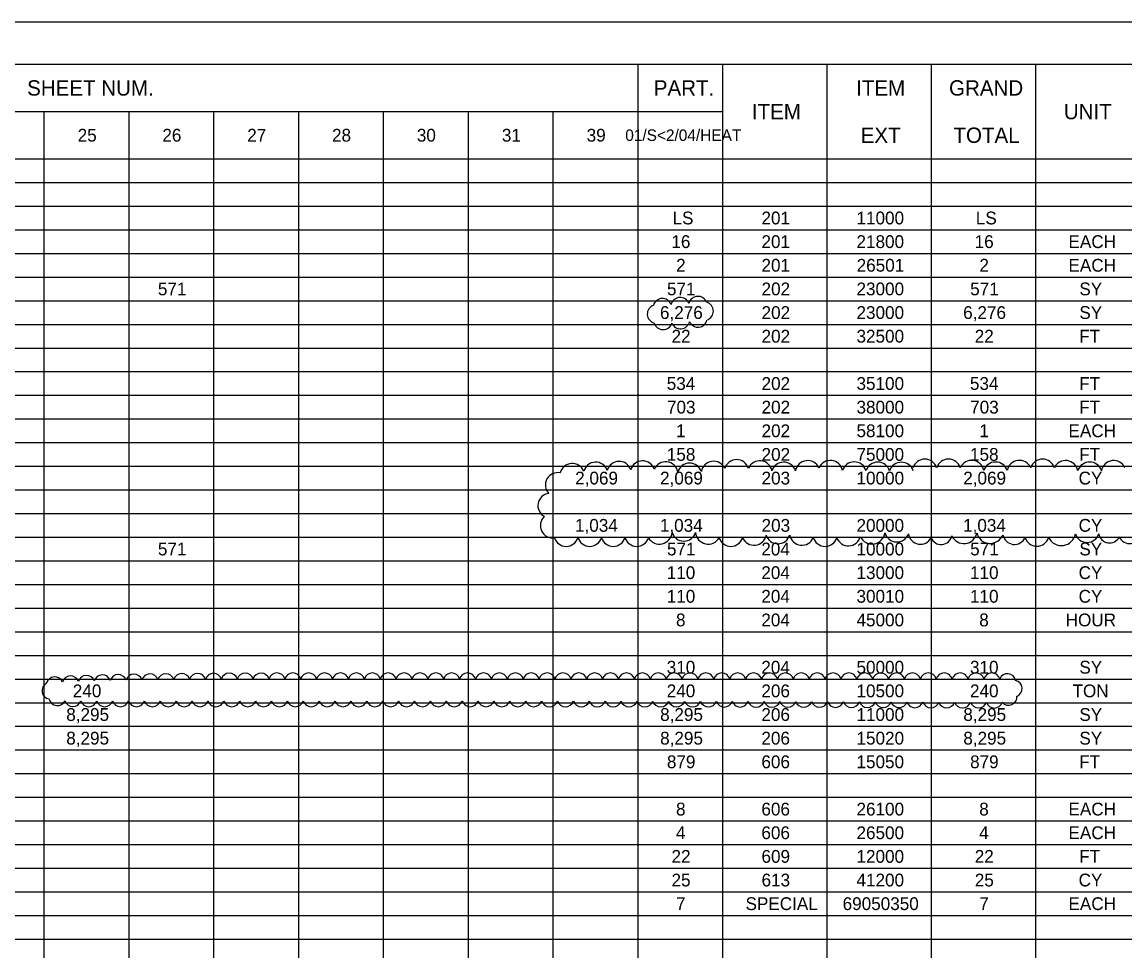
# Model space of a CAD drawing. Extents: x 0 to 36.7, y 0 to 22.
# Drawn here: x 7.27 to 20.33, y 11 to 22 of the extents above; entities that cross this region are included whole.
import ezdxf

# ---------------------------------------------------------------- set-up
doc = ezdxf.new("R2010")
doc.units = 0
for name, color, linetype in [('Default', 7, 'Continuous'), ('SC_Scratch2', 7, 'Continuous'), ('SH_Border', 7, 'Continuous'), ('SH_Cut_Line', 7, 'Continuous')]:
    doc.layers.add(name, color=color, linetype=linetype)

msp = doc.modelspace()

# ---------------------------------------------------------------- linework, layer by layer
at = {"layer": 'Default'}
for p, q in [((1.5, 21.5), (32, 21.5)), ((14.56, 21.5), (14.56, 0.5)), ((15.564, 21.5), (15.564, 0.5)), ((16.799, 21.5), (16.799, 0.5)), ((18.035, 21.5), (18.035, 0.5)), ((19.27, 21.5), (19.27, 0.5)), ((1.5, 20.94), (15.564, 20.94)), ((7.528, 20.94), (7.528, 0.5)), ((8.532, 20.94), (8.532, 0.5)), ((9.537, 20.94), (9.537, 0.5)), ((10.541, 20.94), (10.541, 0.5)), ((11.546, 20.94), (11.546, 0.5)), ((12.55, 20.94), (12.55, 0.5)), ((13.555, 20.94), (13.555, 0.5)), ((1.5, 20.38), (32, 20.38)), ((1.5, 20.1), (32, 20.1)), ((1.5, 19.82), (32, 19.82)), ((1.5, 19.54), (32, 19.54)), ((1.5, 19.26), (32, 19.26)), ((1.5, 18.98), (32, 18.98)), ((1.5, 18.7), (32, 18.7)), ((1.5, 18.42), (32, 18.42)), ((1.5, 18.14), (32, 18.14)), ((1.5, 17.86), (32, 17.86)), ((1.5, 17.58), (32, 17.58)), ((1.5, 17.3), (32, 17.3)), ((1.5, 17.02), (32, 17.02)), ((1.5, 16.74), (32, 16.74)), ((1.5, 16.46), (32, 16.46)), ((1.5, 16.18), (32, 16.18)), ((1.5, 15.9), (32, 15.9)), ((1.5, 15.62), (32, 15.62)), ((1.5, 15.34), (32, 15.34)), ((1.5, 15.06), (32, 15.06)), ((1.5, 14.78), (32, 14.78)), ((1.5, 14.5), (32, 14.5)), ((1.5, 14.22), (32, 14.22)), ((1.5, 13.94), (32, 13.94)), ((1.5, 13.66), (32, 13.66)), ((1.5, 13.38), (32, 13.38)), ((1.5, 13.1), (32, 13.1)), ((1.5, 12.82), (32, 12.82)), ((1.5, 12.54), (32, 12.54)), ((1.5, 12.26), (32, 12.26)), ((1.5, 11.98), (32, 11.98)), ((1.5, 11.7), (32, 11.7)), ((1.5, 11.42), (32, 11.42)), ((1.5, 11.14), (32, 11.14))]:
    msp.add_line(p, q, dxfattribs=at)
at = {"layer": 'SC_Scratch2'}
for centre, radius, start, end in [((14.851, 18.617), 0.11, 20.4379, 165.4379), ((15.061, 18.629), 0.11, 20.96, 165.96), ((15.272, 18.642), 0.11, 21.0791, 166.0791), ((15.344, 18.576), 0.11, 288.5716, 73.5716), ((14.782, 18.542), 0.11, 110.3076, 255.3076), ((14.859, 18.468), 0.11, 197.4518, 342.4518), ((15.065, 18.476), 0.11, 202.0873, 347.0873), ((15.273, 18.494), 0.108, 202.9538, 347.9538), ((13.783, 16.627), 0.146, 21.4169, 166.4169), ((14.06, 16.642), 0.146, 19.6954, 164.6954), ((14.338, 16.651), 0.146, 19.0371, 164.0371), ((14.616, 16.658), 0.146, 18.6594, 163.6594), ((14.889, 16.645), 0.147, 11.1599, 156.1599), ((15.173, 16.631), 0.146, 18.2211, 163.2211), ((15.457, 16.652), 0.147, 25.3014, 170.3014), ((15.73, 16.672), 0.146, 17.9636, 162.9636), ((16.004, 16.657), 0.147, 10.8854, 155.8854), ((16.287, 16.642), 0.146, 17.7891, 162.7891), ((16.571, 16.66), 0.147, 24.6956, 169.6956), ((16.839, 16.661), 0.147, 10.707, 155.707), ((17.123, 16.645), 0.146, 17.6083, 162.6083), ((17.401, 16.643), 0.146, 16.7917, 161.7917), ((17.68, 16.642), 0.146, 17.5196, 162.5196), ((17.959, 16.679), 0.146, 17.5, 162.5), ((18.238, 16.679), 0.146, 17.5, 162.5), ((18.511, 16.662), 0.147, 10.3144, 155.3144), ((18.795, 16.644), 0.146, 17.5, 162.5), ((19.079, 16.662), 0.147, 24.6856, 169.6856), ((19.352, 16.679), 0.146, 17.5, 162.5), ((19.625, 16.661), 0.147, 10.1962, 155.1962), ((19.91, 16.644), 0.146, 17.5, 162.5), ((20.194, 16.661), 0.147, 24.8038, 169.8038), ((13.611, 16.518), 0.146, 78.2198, 223.2198), ((13.522, 16.273), 0.146, 96.8264, 241.8264), ((13.552, 16.037), 0.146, 132.7451, 277.7451), ((14.816, 15.968), 0.15, 210.0865, 355.0865), ((15.105, 15.999), 0.146, 197.5, 342.5), ((15.393, 15.968), 0.15, 184.9135, 329.9135), ((17.333, 15.974), 0.155, 206.5092, 351.5092), ((17.627, 15.989), 0.146, 195.0241, 340.0241), ((17.905, 15.958), 0.142, 187.6612, 332.6612), ((18.421, 15.979), 0.155, 204.1248, 349.1248), ((18.731, 15.988), 0.162, 193.3553, 338.3553), ((19.576, 15.968), 0.168, 205.2375, 350.2375), ((19.88, 15.984), 0.146, 197.9428, 342.9428), ((20.146, 15.96), 0.128, 188.3479, 333.3479), ((20.383, 15.959), 0.135, 204.6591, 349.6591), ((13.711, 15.937), 0.146, 197.5, 342.5), ((13.99, 15.937), 0.146, 197.5, 342.5), ((14.269, 15.937), 0.146, 197.5, 342.5), ((14.547, 15.937), 0.146, 197.5, 342.5), ((15.662, 15.937), 0.146, 197.5, 342.5), ((15.936, 15.952), 0.147, 203.9369, 348.9369), ((16.219, 15.968), 0.146, 197.5, 342.5), ((16.503, 15.952), 0.147, 191.0631, 336.0631), ((16.777, 15.937), 0.146, 197.5, 342.5), ((17.053, 15.943), 0.146, 199.9759, 344.9759), ((18.151, 15.944), 0.131, 202.8141, 347.8141), ((19.019, 15.953), 0.139, 190.3783, 335.3783), ((19.284, 15.939), 0.146, 197.7653, 342.7653), ((7.656, 14.147), 0.0986, 21.8783, 166.8783), ((7.843, 14.158), 0.0986, 20.1463, 165.1463), ((8.031, 14.165), 0.0986, 19.4158, 164.4158), ((8.219, 14.171), 0.0986, 18.9841, 163.9841), ((8.407, 14.175), 0.0986, 18.6903, 163.6903), ((8.595, 14.179), 0.0986, 18.4736, 163.4736), ((8.783, 14.182), 0.0986, 18.3053, 163.3053), ((8.971, 14.184), 0.0986, 18.1697, 163.1697), ((9.159, 14.186), 0.0986, 18.0573, 163.0573), ((9.347, 14.188), 0.0986, 17.9622, 162.9622), ((9.535, 14.189), 0.0986, 17.8805, 162.8805), ((9.723, 14.191), 0.0986, 17.8091, 162.8091), ((9.911, 14.191), 0.0986, 17.7462, 162.7462), ((10.099, 14.192), 0.0986, 17.6901, 162.6901), ((10.287, 14.193), 0.0986, 17.6398, 162.6398), ((10.475, 14.193), 0.0986, 17.5942, 162.5942), ((10.663, 14.193), 0.0986, 17.5527, 162.5527), ((10.851, 14.193), 0.0986, 17.5149, 162.5149), ((11.039, 14.193), 0.0986, 17.5, 162.5), ((11.227, 14.193), 0.0986, 17.5, 162.5), ((11.416, 14.193), 0.0986, 17.5, 162.5), ((11.604, 14.193), 0.0986, 17.5, 162.5), ((11.792, 14.193), 0.0986, 17.5, 162.5), ((11.98, 14.193), 0.0986, 17.5, 162.5), ((12.168, 14.193), 0.0986, 17.5, 162.5), ((12.356, 14.193), 0.0986, 17.5, 162.5), ((12.544, 14.193), 0.0986, 17.5, 162.5), ((12.732, 14.193), 0.0986, 17.5, 162.5), ((12.92, 14.193), 0.0986, 17.5, 162.5), ((13.109, 14.193), 0.0986, 17.5, 162.5), ((13.297, 14.193), 0.0986, 17.5, 162.5), ((13.485, 14.193), 0.0986, 17.5, 162.5), ((13.673, 14.193), 0.0986, 17.5, 162.5), ((13.861, 14.193), 0.0986, 17.5, 162.5), ((14.049, 14.193), 0.0986, 17.5, 162.5), ((14.237, 14.193), 0.0986, 17.5, 162.5), ((14.425, 14.193), 0.0986, 17.5, 162.5), ((14.613, 14.193), 0.0986, 17.5, 162.5), ((14.802, 14.193), 0.0986, 17.5, 162.5), ((14.99, 14.193), 0.0986, 17.5, 162.5), ((15.178, 14.193), 0.0986, 17.5, 162.5), ((15.366, 14.193), 0.0986, 17.5, 162.5), ((15.554, 14.193), 0.0986, 17.5, 162.5), ((15.742, 14.193), 0.0986, 17.5, 162.5), ((15.93, 14.193), 0.0986, 17.5, 162.5), ((16.118, 14.193), 0.0986, 17.5, 162.5), ((16.306, 14.193), 0.0986, 17.5, 162.5), ((16.495, 14.193), 0.0986, 17.5, 162.5), ((16.683, 14.193), 0.0986, 17.5, 162.5), ((16.871, 14.193), 0.0986, 17.5, 162.5), ((17.059, 14.193), 0.0986, 17.5, 162.5), ((17.247, 14.193), 0.0986, 17.5, 162.5), ((17.435, 14.193), 0.0986, 17.5, 162.5), ((17.623, 14.193), 0.0986, 17.5, 162.5), ((17.811, 14.193), 0.0986, 17.5, 162.5), ((17.999, 14.193), 0.0986, 17.5, 162.5), ((18.188, 14.193), 0.0986, 17.5, 162.5), ((18.376, 14.193), 0.0986, 17.5, 162.5), ((18.564, 14.193), 0.0986, 17.5, 162.5), ((18.752, 14.193), 0.0986, 17.5, 162.5), ((18.936, 14.184), 0.0986, 11.6249, 156.6249), ((7.604, 14.081), 0.0985, 116.5401, 261.5401), ((19.012, 14.108), 0.0986, 292.4476, 77.4476), ((7.687, 14.003), 0.0986, 191.4507, 336.4507), ((18.951, 14.008), 0.0986, 219.9453, 4.9453), ((7.871, 13.992), 0.0986, 196.8954, 341.8954), ((8.059, 13.991), 0.0986, 197.5, 342.5), ((8.247, 13.991), 0.0986, 197.5, 342.5), ((8.435, 13.991), 0.0986, 197.5, 342.5), ((8.623, 13.991), 0.0986, 197.5, 342.5), ((8.812, 13.991), 0.0986, 197.5, 342.5), ((9, 13.991), 0.0986, 197.5, 342.5), ((9.188, 13.991), 0.0986, 197.5, 342.5), ((9.376, 13.991), 0.0986, 197.5, 342.5), ((9.564, 13.991), 0.0986, 197.5, 342.5), ((9.752, 13.991), 0.0986, 197.5, 342.5), ((9.94, 13.991), 0.0986, 197.5, 342.5), ((10.128, 13.991), 0.0986, 197.5, 342.5), ((10.316, 13.991), 0.0986, 197.5, 342.5), ((10.505, 13.991), 0.0986, 197.5, 342.5), ((10.693, 13.991), 0.0986, 197.5, 342.5), ((10.881, 13.991), 0.0986, 197.5, 342.5), ((11.069, 13.991), 0.0986, 197.5, 342.5), ((11.257, 13.991), 0.0986, 197.5, 342.5), ((11.445, 13.991), 0.0986, 197.5, 342.5), ((11.633, 13.991), 0.0986, 197.4999, 342.4999), ((11.821, 13.991), 0.0986, 197.4971, 342.4971), ((12.009, 13.991), 0.0986, 197.493, 342.493), ((12.198, 13.991), 0.0986, 197.4887, 342.4887), ((12.386, 13.991), 0.0986, 197.4843, 342.4843), ((12.574, 13.991), 0.0986, 197.4797, 342.4797), ((12.762, 13.991), 0.0986, 197.4749, 342.4749), ((12.95, 13.991), 0.0986, 197.4698, 342.4698), ((13.138, 13.991), 0.0986, 197.4646, 342.4646), ((13.326, 13.991), 0.0986, 197.4591, 342.4591), ((13.514, 13.99), 0.0986, 197.4534, 342.4534), ((13.702, 13.99), 0.0986, 197.4474, 342.4474), ((13.891, 13.99), 0.0986, 197.4411, 342.4411), ((14.079, 13.99), 0.0986, 197.4345, 342.4345), ((14.267, 13.99), 0.0986, 197.4276, 342.4276), ((14.455, 13.989), 0.0986, 197.4202, 342.4202), ((14.643, 13.989), 0.0986, 197.4125, 342.4125), ((14.831, 13.989), 0.0986, 197.4042, 342.4042), ((15.019, 13.989), 0.0986, 197.3955, 342.3955), ((15.207, 13.988), 0.0986, 197.3862, 342.3862), ((15.395, 13.988), 0.0986, 197.3763, 342.3763), ((15.584, 13.987), 0.0986, 197.3657, 342.3657), ((15.772, 13.987), 0.0986, 197.3544, 342.3544), ((15.96, 13.986), 0.0986, 197.3421, 342.3421), ((16.148, 13.986), 0.0986, 197.3289, 342.3289), ((16.336, 13.985), 0.0986, 197.3145, 342.3145), ((16.524, 13.985), 0.0986, 197.2987, 342.2987), ((16.712, 13.984), 0.0986, 197.2815, 342.2815), ((16.9, 13.983), 0.0986, 197.2625, 342.2625), ((17.088, 13.982), 0.0986, 197.2432, 342.2432), ((17.277, 13.982), 0.0986, 197.2392, 342.2392), ((17.465, 13.981), 0.0986, 197.2392, 342.2392), ((17.653, 13.98), 0.0986, 197.2392, 342.2392), ((17.841, 13.979), 0.0986, 197.2392, 342.2392), ((18.029, 13.978), 0.0986, 197.2392, 342.2392), ((18.217, 13.977), 0.0986, 197.2392, 342.2392), ((18.405, 13.976), 0.0986, 197.2392, 342.2392), ((18.593, 13.976), 0.0986, 197.2392, 342.2392), ((18.781, 13.975), 0.0986, 197.2392, 342.2392)]:
    msp.add_arc(centre, radius, start, end, dxfattribs=at)
at = {"layer": 'SH_Border'}
msp.add_lwpolyline([(1.5, 21.5), (33.5, 21.5), (33.5, 0.5), (1.5, 0.5)], close=True, dxfattribs=at)
at = {"layer": 'SH_Cut_Line'}
msp.add_lwpolyline([(0, 0), (34, 0), (34, 22), (0, 22)], close=True, dxfattribs=at)

# ---------------------------------------------------------------- texts
at = {"layer": 'Default'}
for s, height, p in [('SHEET NUM.', 0.1818, (7.329, 21.129)), ('PART.', 0.1818, (14.749, 21.129)), ('ITEM', 0.1818, (17.145, 21.129)), ('GRAND', 0.1818, (18.245, 21.129)), ('ITEM', 0.1818, (15.91, 20.849)), ('UNIT', 0.1818, (19.604, 20.849)), ('25', 0.1515, (7.927, 20.584)), ('26', 0.1515, (8.93, 20.584)), ('27', 0.1515, (9.935, 20.584)), ('28', 0.1515, (10.939, 20.584)), ('30', 0.1515, (11.943, 20.584)), ('31', 0.1515, (12.95, 20.584)), ('39', 0.1515, (13.954, 20.584)), ('01/S<2/04/HEAT', 0.13638, (14.411, 20.592)), ('EXT', 0.1818, (17.199, 20.569)), ('TOTAL', 0.1818, (18.297, 20.569)), ('LS', 0.1515, (14.971, 19.604)), ('201', 0.1515, (16.024, 19.604)), ('11000', 0.1515, (17.149, 19.604)), ('LS', 0.1515, (18.562, 19.604)), ('16', 0.1515, (14.957, 19.324)), ('201', 0.1515, (16.024, 19.324)), ('21800', 0.1515, (17.149, 19.324)), ('16', 0.1515, (18.548, 19.324)), ('EACH', 0.1515, (19.659, 19.324)), ('2', 0.152, (15.013, 19.044)), ('201', 0.1515, (16.024, 19.044)), ('26501', 0.1515, (17.151, 19.044)), ('2', 0.152, (18.604, 19.044)), ('EACH', 0.1515, (19.659, 19.044)), ('571', 0.1515, (8.877, 18.764)), ('571', 0.1515, (14.905, 18.764)), ('202', 0.1515, (16.025, 18.764)), ('23000', 0.1515, (17.149, 18.764)), ('571', 0.1515, (18.495, 18.764)), ('SY', 0.1515, (19.788, 18.764)), ('6,276', 0.1515, (14.822, 18.484)), ('202', 0.1515, (16.025, 18.484)), ('23000', 0.1515, (17.149, 18.484)), ('6,276', 0.1515, (18.412, 18.484)), ('SY', 0.1515, (19.788, 18.484)), ('22', 0.1515, (14.959, 18.204)), ('202', 0.1515, (16.025, 18.204)), ('32500', 0.1515, (17.149, 18.204)), ('22', 0.1515, (18.549, 18.204)), ('FT', 0.1515, (19.786, 18.204)), ('534', 0.1515, (14.902, 17.644)), ('202', 0.1515, (16.025, 17.644)), ('35100', 0.1515, (17.149, 17.644)), ('534', 0.1515, (18.492, 17.644)), ('FT', 0.1515, (19.786, 17.644)), ('703', 0.1515, (14.905, 17.364)), ('202', 0.1515, (16.025, 17.364)), ('38000', 0.1515, (17.149, 17.364)), ('703', 0.1515, (18.495, 17.364)), ('FT', 0.1515, (19.786, 17.364)), ('202', 0.1515, (16.025, 17.084)), ('58100', 0.1515, (17.149, 17.084)), ('EACH', 0.1515, (19.659, 17.084)), ('1', 0.152, (15.013, 17.084)), ('1', 0.152, (18.604, 17.084)), ('158', 0.1515, (14.903, 16.804)), ('202', 0.1515, (16.025, 16.804)), ('75000', 0.1515, (17.149, 16.804)), ('158', 0.1515, (18.493, 16.804)), ('FT', 0.1515, (19.786, 16.804)), ('2,069', 0.1515, (13.818, 16.524)), ('2,069', 0.1515, (14.823, 16.524)), ('203', 0.1515, (16.025, 16.524)), ('10000', 0.1515, (17.149, 16.524)), ('2,069', 0.1515, (18.413, 16.524)), ('CY', 0.1515, (19.779, 16.524)), ('1,034', 0.1515, (13.816, 15.964)), ('1,034', 0.1515, (14.821, 15.964)), ('203', 0.1515, (16.025, 15.964)), ('20000', 0.1515, (17.149, 15.964)), ('1,034', 0.1515, (18.411, 15.964)), ('CY', 0.1515, (19.779, 15.964)), ('571', 0.1515, (8.877, 15.684)), ('571', 0.1515, (14.905, 15.684)), ('204', 0.1515, (16.022, 15.684)), ('10000', 0.1515, (17.149, 15.684)), ('571', 0.1515, (18.495, 15.684)), ('SY', 0.1515, (19.788, 15.684)), ('110', 0.1515, (14.902, 15.404)), ('204', 0.1515, (16.022, 15.404)), ('13000', 0.1515, (17.149, 15.404)), ('110', 0.1515, (18.493, 15.404)), ('CY', 0.1515, (19.779, 15.404)), ('110', 0.1515, (14.902, 15.124)), ('204', 0.1515, (16.022, 15.124)), ('30010', 0.1515, (17.149, 15.124)), ('110', 0.1515, (18.493, 15.124)), ('CY', 0.1515, (19.779, 15.124)), ('8', 0.152, (15.012, 14.844)), ('204', 0.1515, (16.022, 14.844)), ('45000', 0.1515, (17.149, 14.844)), ('8', 0.152, (18.602, 14.844)), ('HOUR', 0.1515, (19.626, 14.844)), ('310', 0.1515, (14.902, 14.284)), ('204', 0.1515, (16.022, 14.284)), ('50000', 0.1515, (17.149, 14.284)), ('310', 0.1515, (18.493, 14.284)), ('SY', 0.1515, (19.788, 14.284)), ('240', 0.1515, (7.87, 14.004)), ('240', 0.1515, (14.902, 14.004)), ('206', 0.1515, (16.023, 14.004)), ('10500', 0.1515, (17.149, 14.004)), ('240', 0.1515, (18.493, 14.004)), ('TON', 0.1515, (19.707, 14.004)), ('8,295', 0.1515, (7.792, 13.724)), ('8,295', 0.1515, (14.824, 13.724)), ('206', 0.1515, (16.023, 13.724)), ('11000', 0.1515, (17.149, 13.724)), ('8,295', 0.1515, (18.414, 13.724)), ('SY', 0.1515, (19.788, 13.724)), ('8,295', 0.1515, (7.792, 13.444)), ('8,295', 0.1515, (14.824, 13.444)), ('206', 0.1515, (16.023, 13.444)), ('15020', 0.1515, (17.149, 13.444)), ('8,295', 0.1515, (18.414, 13.444)), ('SY', 0.1515, (19.788, 13.444)), ('879', 0.1515, (14.904, 13.164)), ('606', 0.1515, (16.023, 13.164)), ('15050', 0.1515, (17.149, 13.164)), ('879', 0.1515, (18.494, 13.164)), ('FT', 0.1515, (19.786, 13.164)), ('8', 0.152, (15.012, 12.604)), ('606', 0.1515, (16.023, 12.604)), ('26100', 0.1515, (17.149, 12.604)), ('8', 0.152, (18.602, 12.604)), ('EACH', 0.1515, (19.659, 12.604)), ('4', 0.152, (15.011, 12.324)), ('606', 0.1515, (16.023, 12.324)), ('26500', 0.1515, (17.149, 12.324)), ('4', 0.152, (18.601, 12.324)), ('EACH', 0.1515, (19.659, 12.324)), ('22', 0.1515, (14.959, 12.044)), ('609', 0.1515, (16.024, 12.044)), ('12000', 0.1515, (17.149, 12.044)), ('22', 0.1515, (18.549, 12.044)), ('FT', 0.1515, (19.786, 12.044)), ('25', 0.1515, (14.959, 11.764)), ('613', 0.1515, (16.025, 11.764)), ('41200', 0.1515, (17.149, 11.764)), ('25', 0.1515, (18.55, 11.764)), ('CY', 0.1515, (19.779, 11.764)), ('7', 0.152, (15.012, 11.484)), ('SPECIAL', 0.1515, (15.835, 11.484)), ('69050350', 0.1515, (16.985, 11.484)), ('7', 0.152, (18.603, 11.484)), ('EACH', 0.1515, (19.659, 11.484))]:
    msp.add_text(s, height=height, dxfattribs=at).set_placement(p)

doc.saveas('drawing.dxf')
